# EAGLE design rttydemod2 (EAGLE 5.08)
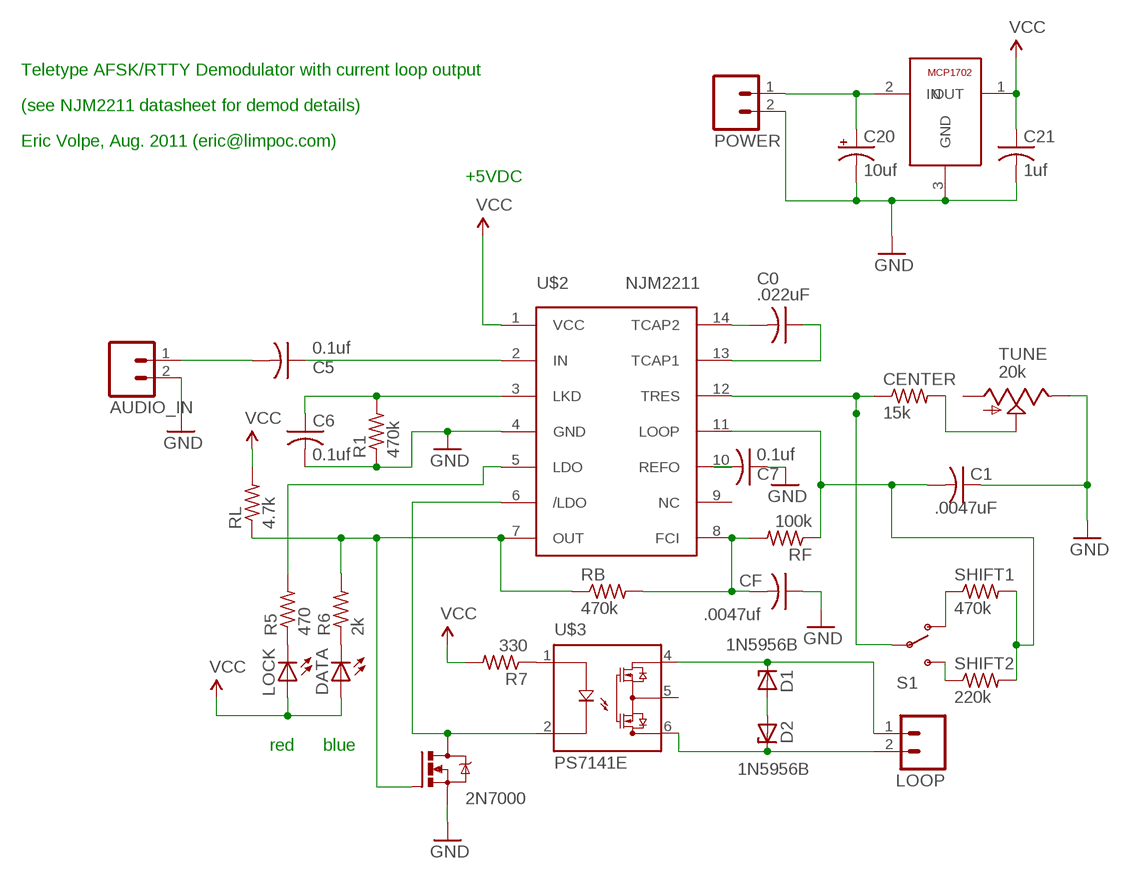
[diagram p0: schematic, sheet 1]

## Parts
AUDIO_IN  M023.5MM  [SCREWTERMINAL-3.5MM-2]
C0  .022uF  C-US025-030X050  [C025-030X050]
C1  .0047uF  C-US025-030X050  [C025-030X050]
C5  0.1uf  C-US025-030X050  [C025-030X050]
C6  0.1uf  C-US025-030X050  [C025-030X050]
C7  0.1uf  C-US025-030X050  [C025-030X050]
C20  10uf  CPOL-USB45181A  [B45181A]
C21  1uf  C-US025-030X050  [C025-030X050]
CENTER  15k  R-US_0204/7  [0204/7]
CF  .0047uf  C-US025-030X050  [C025-030X050]
D1  1N5956B  ZENER-DIODEDO41Z10  [DO41Z10]
D2  1N5956B  ZENER-DIODEDO41Z10  [DO41Z10]
DATA  LED3MM  [LED3MM]
LOCK  LED3MM  [LED3MM]
LOOP  M023.5MM  [SCREWTERMINAL-3.5MM-2]
POWER  M023.5MM  [SCREWTERMINAL-3.5MM-2]
R1  470k  R-US_0204/7  [0204/7]
R5  470  R-US_0204/7  [0204/7]
R6  2k  R-US_0204/7  [0204/7]
R7  330  R-US_0204/7  [0204/7]
RB  470k  R-US_0204/7  [0204/7]
RF  100k  R-US_0204/7  [0204/7]
RL  4.7k  R-US_0204/7  [0204/7]
S1  SWITCH-SPSTPTH  [SWITCH-SPDT]
SHIFT1  470k  R-US_0204/7  [0204/7]
SHIFT2  220k  R-US_0204/7  [0204/7]
TUNE  20k  TRIM_US-RJ9W  [RJ9W]
U$1  MCP1702  [TO92A]
U$2  NJM2211  [DIL14]
U$3  PS7141E  AQV257  [DIL06]
U$4  2N7000  VN10LM  [TO92A]

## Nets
GND: AUDIO_IN.2 C1.1 C6.2 C7.1 C20.- C21.2 CF.1 POWER.2 R1.1 TUNE.E U$1.3(GND) U$2.4(GND) U$4.3(S)
N$1: D2.C LOOP.2 U$3.6(DRN2)
N$2: U$2.6(/LDO) U$3.2(CAT) U$4.1(D)
N$3: D1.C LOOP.1 U$3.4(DRN1)
N$4: R6.2 RB.1 RL.1 U$2.7(OUT) U$4.2(G)
N$5: C5.1 U$2.2(IN)
N$6: CF.2 RB.2 RF.2 U$2.8(FCI)
N$7: CENTER.2 TUNE.S
N$8: CENTER.1 S1.2(P) U$2.12(TRES)
N$9: C0.2 U$2.14(TCAP2)
N$10: C0.1 U$2.13(TCAP1)
N$11: C6.1 R1.2 U$2.3(LKD)
N$12: C20.+ POWER.1 U$1.2(IN)
N$13: S1.3(S) SHIFT2.1
N$14: S1.1(O) SHIFT1.1
N$15: LOCK.K(C) R5.1
N$16: R5.2 U$2.5(LDO)
N$17: C1.2 RF.1 SHIFT1.2 SHIFT2.2 U$2.11(LOOP)
N$18: AUDIO_IN.1 C5.2
N$19: DATA.K(C) R6.1
N$20: C7.2 U$2.10(REFO)
N$21: R7.1 U$3.1(ANO)
N$22: D1.A D2.A
VCC: C21.1 DATA.A LOCK.A R7.2 RL.2 U$1.1(OUT) U$2.1(VCC)
Unconnected: TUNE.A U$2.9(NC) U$3.5(COM)

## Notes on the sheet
- Teletype AFSK/RTTY Demodulator with current loop output
- (see NJM2211 datasheet for demod details)
- Eric Volpe, Aug. 2011 (eric@limpoc.com)
- +5VDC
- red | blue

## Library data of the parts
AUDIO_IN LOOP POWER = SparkFun:M02: Header 2
C0 C1 C5-C7 C21 CF = rcl:C-US: CAPACITOR, American symbol
C20 = rcl:CPOL-US: POLARIZED CAPACITOR, American symbol
CENTER R1 R5-R7 RB RF RL SHIFT1 SHIFT2 = rcl:R-US_: RESISTOR, American symbol
D1 D2 = diode:ZENER-DIODE: Z-Diode
DATA LOCK = SparkFun:LED: LEDs
S1 = SparkFun:SWITCH-SPST: SPST Switch Simple slide switch. Spark Fun Electronics SKU : COM-00102
TUNE = pot:TRIM_US-: POTENTIOMETER
U$1 = epv:MCP1702
U$2 = epv:NJM2211: FSK Demodulator from New Japan Radio
U$3 = epv:AQV257
U$4 = epv:VN10LM

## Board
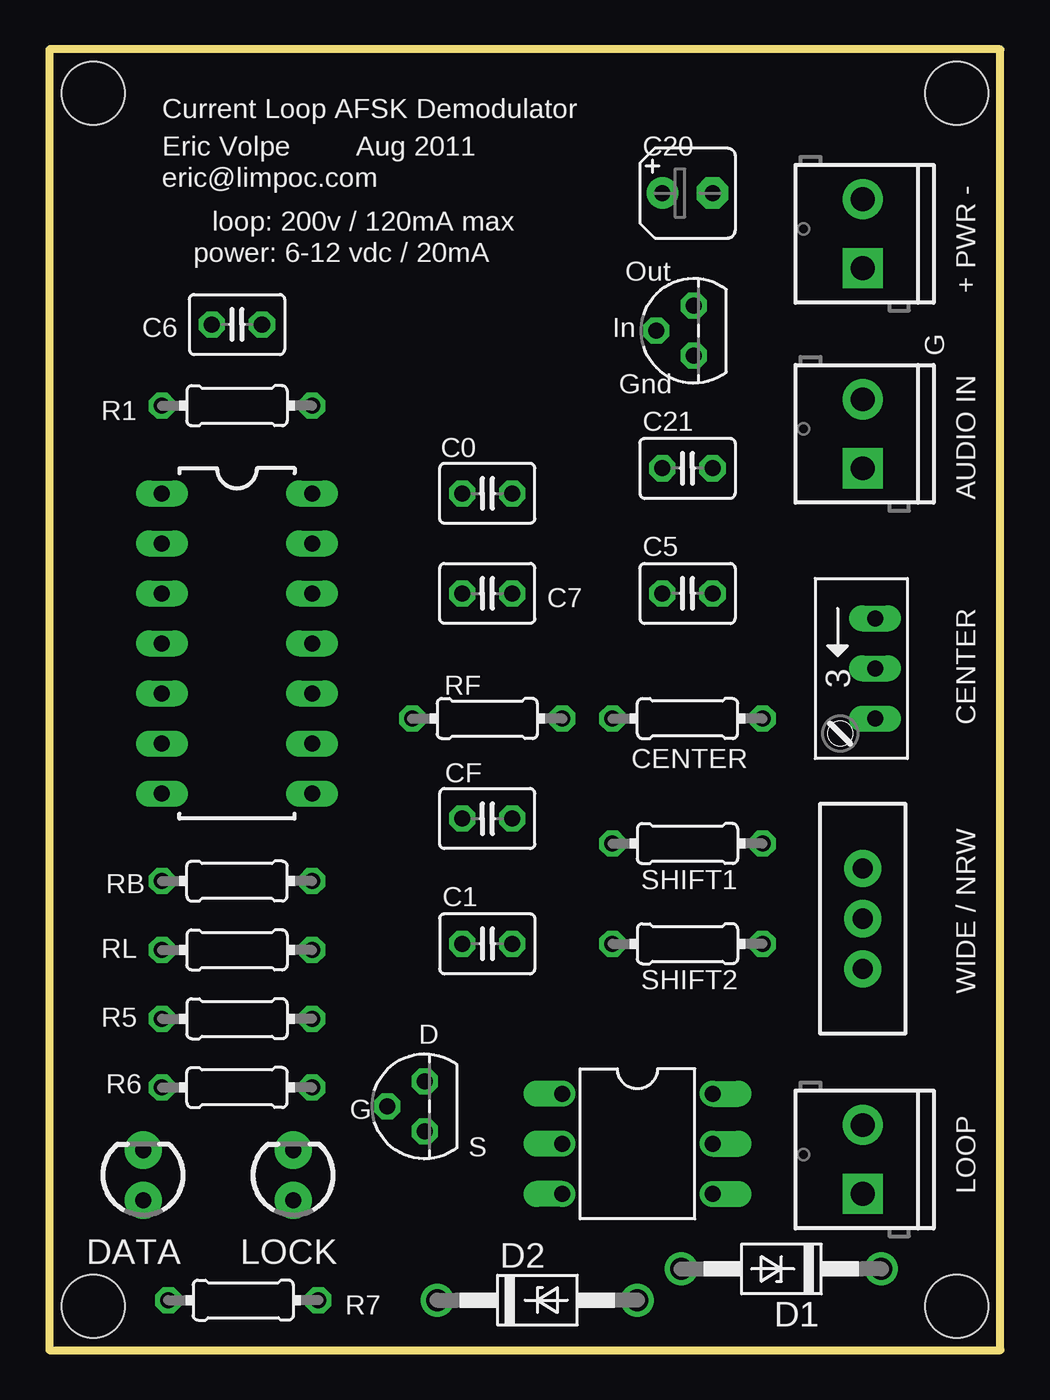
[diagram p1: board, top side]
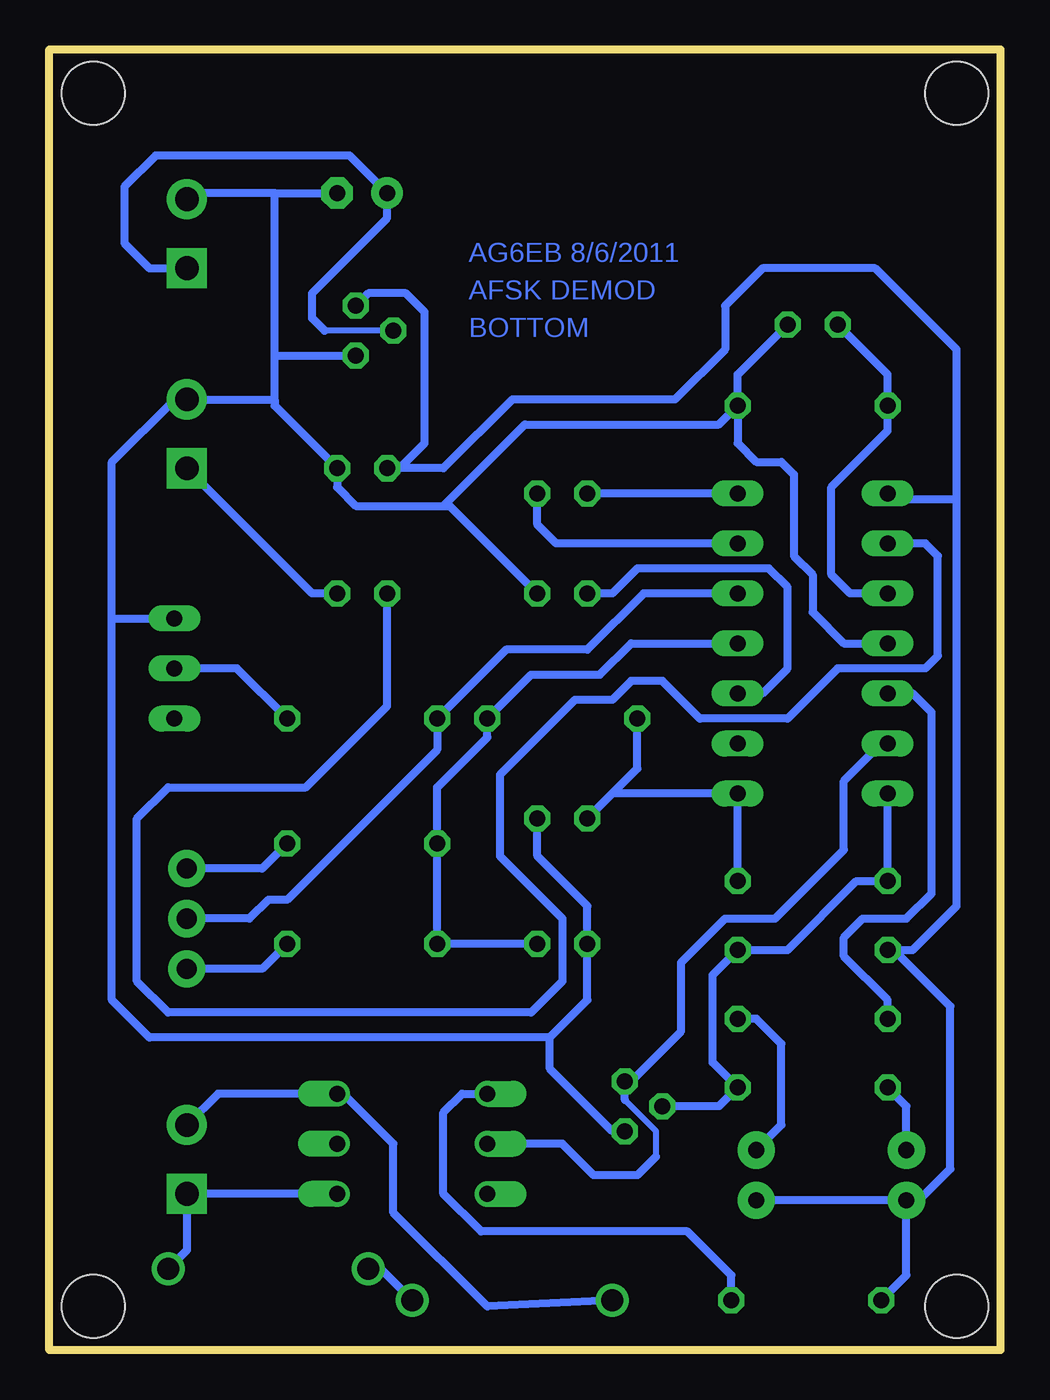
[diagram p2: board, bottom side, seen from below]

Size 48.26 x 66.04 mm. Coordinates in mm from the lower left corner, seen from the top.
Outline: 0,0 48.26,0 48.26,66.04 0,66.04 0,0
Copper layers (1*16): Top 0.035mm / dielectric 1.5mm / Bottom 0.035mm
Design rules "default *": minimum track width 10mil, minimum drill 24mil, track to track 8mil, track to pad 8mil, pad to pad 8mil, via to via 8mil, smd to smd 8mil, copper to edge 40mil, drill to drill 8mil, minimum pad ring 10mil, minimum via ring 8mil, stop-mask expansion 4mil, vias tented up to drill 0mil, thermal gap 10mil
Holes 3.2 mm at 2.22,63.82 2.22,2.22 46.04,2.22 46.04,63.82

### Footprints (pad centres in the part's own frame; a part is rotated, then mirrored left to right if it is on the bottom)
SCREWTERMINAL-3.5MM-2 = drill 1.2 pad 2.032 square: 1 0,0 | drill 1.2 pad 2.032 round: 2 3.5,0
C025-030X050 = drill 0.813 octagon: 1 -1.27,0; 2 1.27,0
B45181A = drill 0.813 pad 1.6 round: + -1.27,0 | drill 0.813 pad 1.6 octagon: - 1.27,0
0204/7 = drill 0.813 octagon: 1 -3.81,0; 2 3.81,0
DO41Z10 = drill 1.118 round: A 5.08,0; C -5.08,0
LED3MM = drill 0.813 pad 1.88 round: A -1.27,0; K 1.27,0
SWITCH-SPDT = drill 1.016 pad 1.88 round: 1 0,2.54; 2 0,0; 3 0,-2.54
RJ9W = drill 0.813 long: A 2.54,0.635; E -2.54,0.635; S 0,0.635
TO92A = drill 0.813 octagon: 1 1.27,0; 2 0,1.905; 3 -1.27,0
DIL14 = drill 0.813 long: 1 -7.62,-3.81; 2 -5.08,-3.81; 3 -2.54,-3.81; 4 0,-3.81; 5 2.54,-3.81; 6 5.08,-3.81; 7 7.62,-3.81; 8 7.62,3.81; 9 5.08,3.81; 10 2.54,3.81; 11 0,3.81; 12 -2.54,3.81; 13 -5.08,3.81; 14 -7.62,3.81
DIL06 = drill 0.813 offset: 1 -2.54,-3.81; 2 0,-3.81; 3 2.54,-3.81; 4 2.54,3.81; 5 0,3.81; 6 -2.54,3.81

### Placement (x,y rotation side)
AUDIO_IN  41.27,44.77 90 top
C0  22.23,43.5 180 top
C1  22.23,20.64 0 top
C5  32.38,38.42 0 top
C6  9.53,52.07 0 top
C7  22.23,38.42 180 top
C20  32.38,58.74 0 top
C21  32.38,44.77 0 top
CENTER  32.38,32.07 0 top
CF  22.23,26.99 180 top
D1  37.15,4.13 180 top
D2  24.77,2.54 0 top
DATA  4.76,8.89 90 top
LOCK  12.38,8.89 90 top
LOOP  41.27,7.94 90 top
POWER  41.27,54.93 90 top
R1  9.53,47.94 180 top
R5  9.53,16.83 180 top
R6  9.53,13.34 0 top
R7  9.84,2.54 180 top
RB  9.53,23.81 0 top
RF  22.23,32.07 180 top
RL  9.53,20.32 180 top
S1  41.27,21.91 0 top
SHIFT1  32.38,25.72 180 top
SHIFT2  32.38,20.64 180 top
TUNE  41.27,34.61 270 top
U$1  32.7,51.75 90 top
U$2  9.53,35.88 270 top
U$3  29.84,10.48 270 top
U$4  19.05,12.38 90 top

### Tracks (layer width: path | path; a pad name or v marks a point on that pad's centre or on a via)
GND
  Bottom 0.406: AUDIO_IN.2 41.9,48.27 45.09,45.09 45.09,37.15 | U$2.4 7.94,35.88 9.53,37.47 9.53,39.37 10.48,40.32 10.48,44.45 11.11,45.09 12.38,45.09 13.34,46.04 R1.1 | 28.26,42.86 32.7,42.86 33.66,43.81 C21.2 36.83,47.94 36.83,48.26 | 28.26,42.86 24.13,46.99 14.29,46.99 R1.1 | CF.1 23.5,25.08 20.95,22.54 C1.1 20.95,17.78 22.86,15.88 | C7.1 27.94,42.86 28.26,42.86 | 45.09,37.15 TUNE.E | AUDIO_IN.2 | R1.1 13.34,49.53 C6.2 | POWER.2 40.95,58.74 36.83,58.74 | AUDIO_IN.2 36.84,48.27 36.83,48.26 | 36.83,48.26 36.83,50.48 | 36.83,50.48 36.83,58.74 | 36.83,58.74 C20.- | 36.83,50.48 U$1.3 | 22.86,15.88 43.18,15.88 45.09,17.78 45.09,37.15 | U$4.3 19.68,11.11 22.86,14.29 22.86,15.88
N$1
  Bottom 0.406: LOOP.2 39.7,13.02 U$3.6 33.34,13.02 30.8,10.48 30.8,6.99 26.04,2.22 D2.C
N$2
  Bottom 0.305: 19.05,12.7 17.46,11.11 17.46,9.84
  Bottom 0.406: U$2.6 6.03,30.8 7.94,28.89 7.94,25.4 11.43,21.91 13.97,21.91 16.19,19.68 16.19,16.19 18.73,13.65 U$4.1 19.05,12.7 | 17.46,9.84 18.41,8.89 20.64,8.89 21.43,9.68 21.59,9.84 22.23,10.48 U$3.2
N$3
  Bottom 0.406: U$3.4 LOOP.1 41.27,5.08 D1.C
N$4
  Bottom 0.406: U$2.7 RB.1 7.3,23.81 10.79,20.32 RL.1 14.61,19.05 14.61,14.61 R6.2 14.29,12.38 U$4.2
N$5
  Bottom 0.406: 6.35,40.96 U$2.2 3.81,40.96 3.17,40.32 3.17,35.24 3.81,34.61 8.26,34.61 10.79,32.07 15.24,32.07 17.14,33.97 18.73,33.97 19.68,33.02 21.59,33.02 25.4,29.21 25.4,25.08 22.23,21.91 22.23,18.73 23.81,17.14 42.23,17.14 43.81,18.73 43.81,26.99 42.23,28.57 35.24,28.57 31.11,32.7 C5.1
N$6
  Bottom 0.406: RB.2 U$2.8 19.68,28.26 | 19.68,28.26 CF.2 | RF.2 18.41,29.53 19.68,28.26
N$7
  Bottom 0.406: CENTER.2 38.73,34.61 TUNE.S
N$8
  Bottom 0.406: U$2.12 18.1,38.42 20.95,35.56 25.08,35.56 CENTER.1 28.57,30.48 36.2,22.86 37.15,22.86 38.1,21.91 S1.2
N$9
  Bottom 0.406: U$2.14 C0.2
N$10
  Bottom 0.406: U$2.13 22.54,40.96 23.5,41.91 C0.1
N$11
  Bottom 0.406: 4.76,38.42 U$2.3 7.62,38.42 8.57,39.37 8.57,43.81 5.71,46.67 R1.2 5.71,49.53 C6.1
N$12
  Bottom 0.305: U$1.2 34.29,51.75
  Bottom 0.406: POWER.1 43.18,54.93 44.45,56.2 44.45,59.05 42.86,60.64 33.02,60.64 C20.+ 31.11,57.47 34.92,53.66 34.92,52.39 34.29,51.75
N$13
  Bottom 0.406: SHIFT2.1 37.47,19.37 S1.3
N$14
  Bottom 0.406: SHIFT1.1 37.47,24.45 S1.1
N$15
  Bottom 0.406: LOCK.K 11.11,11.43 11.11,15.56 12.38,16.83 R5.1
N$16
  Bottom 0.406: U$2.5 4.45,33.34 3.49,32.38 3.49,23.18 4.76,21.91 6.99,21.91 7.94,20.95 7.94,20 5.71,17.78 R5.2
N$17
  Bottom 0.406: C1.2 SHIFT2.2 SHIFT1.2 28.57,28.57 26.04,31.11 RF.1 23.81,34.29 20.32,34.29 18.73,35.88 U$2.11
N$18
  Bottom 0.406: C5.2 34.92,38.42 AUDIO_IN.1
N$19
  Bottom 0.406: DATA.K 4.76,12.38 R6.1
N$20
  Bottom 0.406: U$2.10 12.06,33.34 10.79,34.61 10.79,38.73 11.75,39.69 18.41,39.69 19.68,38.42 C7.2
N$21
  Bottom 0.406: U$3.1 27.3,13.02 28.26,12.06 28.26,7.94 26.35,6.03 15.88,6.03 13.65,3.81 R7.1
N$22
  Bottom 0.406: D2.A 31.43,4.13 D1.A
VCC
  Bottom 0.406: 2.22,43.18 2.22,22.54 4.45,20.32 RL.2 5.4,20.32 2.54,17.46 2.54,9.21 4.13,7.62 DATA.A | 2.22,43.18 2.22,50.8 6.35,54.93 12.06,54.93 13.97,53.02 13.97,50.8 16.51,48.26 24.77,48.26 28.26,44.77 C21.1 30.48,44.77 29.21,46.04 29.21,52.7 30.16,53.66 32.07,53.66 U$1.1 | U$2.1 5.4,43.18 2.22,43.18 | DATA.A LOCK.A | R7.2 4.76,3.81 DATA.A

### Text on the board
Bottom: AG6EB 8/6/2011 | AFSK DEMOD | BOTTOM
tPlace: Current Loop AFSK Demodulator | Eric Volpe | Aug 2011 | eric@limpoc.com | + PWR - | AUDIO IN | CENTER | WIDE / NRW | LOOP
tNames: loop: 200v / 120mA max | power: 6-12 vdc / 20mA | Out | In | G | Gnd | D | G | S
